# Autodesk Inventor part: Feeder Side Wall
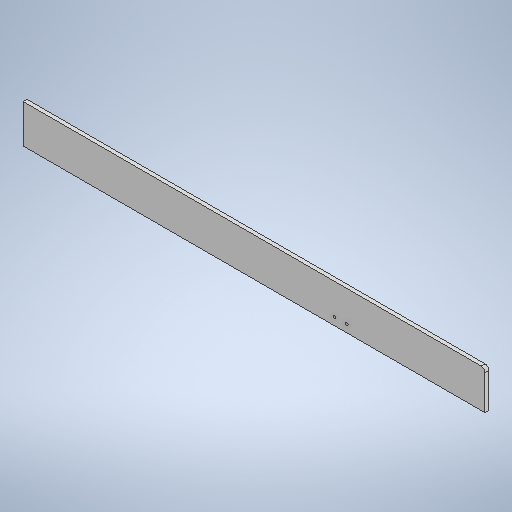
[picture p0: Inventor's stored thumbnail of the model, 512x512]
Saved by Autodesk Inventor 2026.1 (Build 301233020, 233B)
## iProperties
Created: 2026-11
Part Number: Feeder Side Wall
Material: Generic
Document SubType Name: Modeling
Designer: hp
Density: 1 g/cm^3
Appearance: Default
Author: hp
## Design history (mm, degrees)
sketch "Sketch1"
  geometry: L1 (0, 0)-(600, 0); L2 (600, 0)-(600, 50); L3 (600, 50)-(0, 50); L4 (0, 50)-(0, 0)
  constraints: 8 end point, 2 parallel, 1 horizontal, 1 perpendicular
  dimensions: "d0" = 600 distance of L3.end L2.end; "d1" = 50 distance of L2.end L1.end
extrude "Extrusion1" new body sketch "Sketch1" distance "d2" = 5; taper "d3" = 0 deg
sketch "Sketch3"
  geometry: 2 further points
hole "Hole2" sketch "Sketch3" at (404.5, 10), (420.5, 10) diameter "d11" = 3.242; stored, may be unused: countersink angle "d15" = 90 deg, drill point angle "d17" = 120 deg; dims "d12" = 5.5, "d13" = 4, "d14" = 2, "d16" = 6
fillet "Fillet1" dims "d25" = 5
sketch "Sketch5"
  geometry: 2 further points
hole "Hole4" sketch "Sketch5" at (-404.5, 10), (-420.5, 10) diameter "d26" = 3.242; stored, may be unused: countersink angle "d30" = 90 deg, drill point angle "d32" = 120 deg; dims "d27" = 8, "d28" = 4, "d29" = 2, "d31" = 8
body "Solid1"
